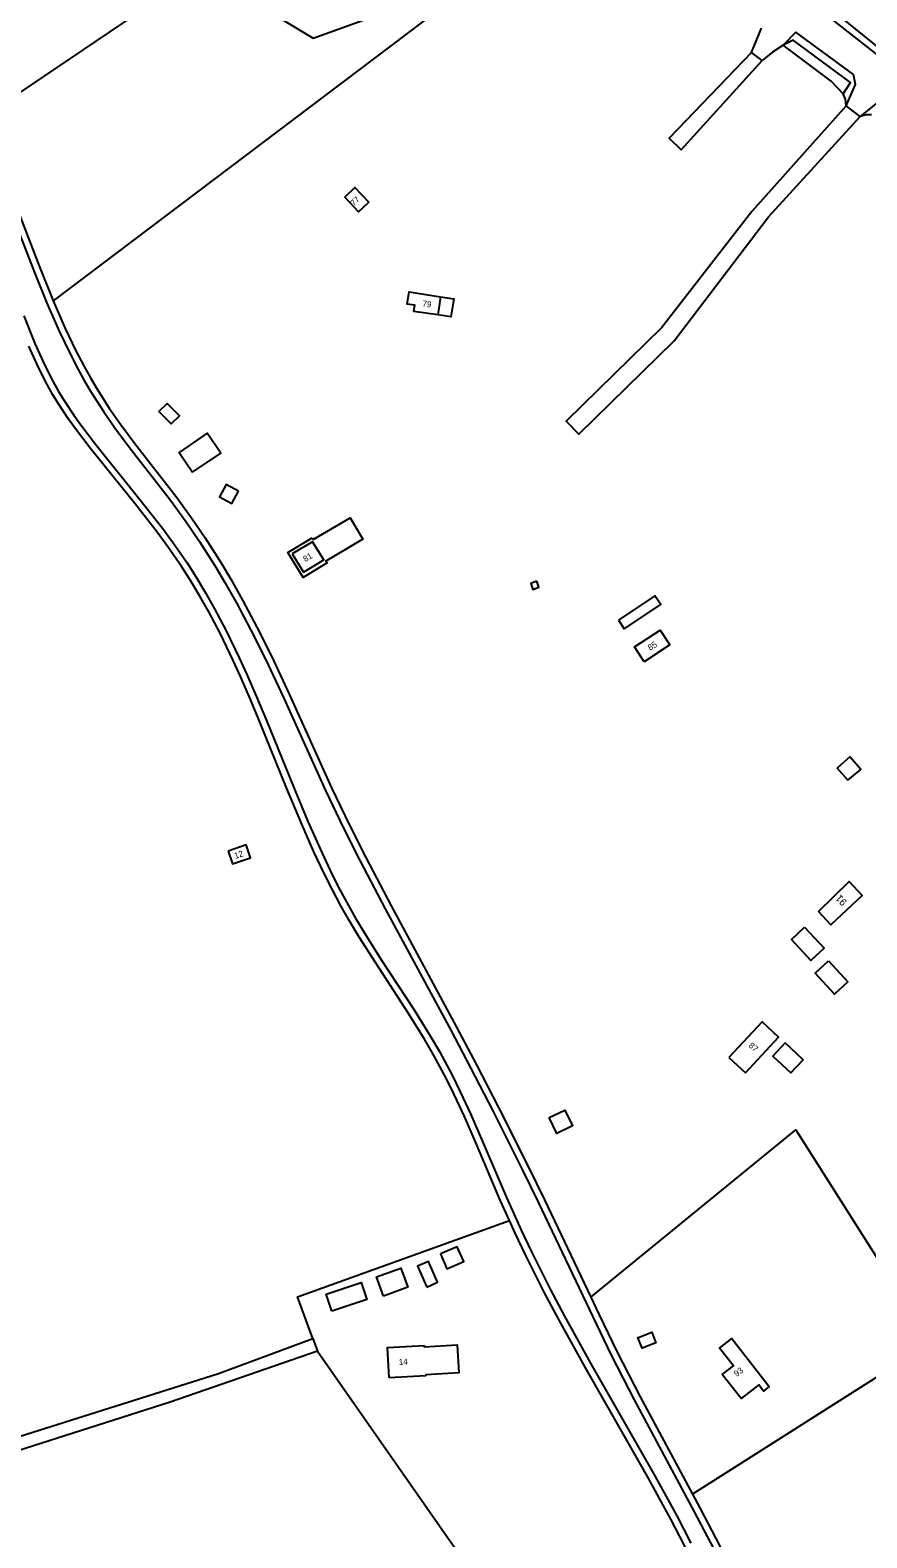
# Model space of a CAD drawing. Extents: x 124000 to 129000, y 395500 to 397503.
# Drawn here: x 128628.5 to 128766.7, y 395626.1 to 395875.2 of the extents above; entities that cross this region are included whole.
import ezdxf

# ---------------------------------------------------------------- set-up
doc = ezdxf.new("R2010")
doc.units = 0
for name, color, linetype in [('gg-afsc-draadraster', 7, 'Continuous'), ('gg-afsc-hekwerk', 7, 'Continuous'), ('gg-anno-huisnummerreeks BGT', 7, 'Continuous'), ('gg-bbg-bijgebouw', 7, 'Continuous'), ('gg-bbg-gedigitaliseerde bijgebouw', 7, 'Continuous'), ('gg-bbg-hoofdgebouw', 7, 'Continuous'), ('gg-bbg-luifel en loopbrug', 7, 'Continuous'), ('gg-bbg-overig bouwwerk', 7, 'Continuous'), ('gg-knt-onverhard', 7, 'Continuous'), ('gg-knt-verharding', 7, 'Continuous'), ('gg-kntw-bovenkant insteek waterloop', 7, 'Continuous'), ('gg-kntw-greppel-droge sloot', 7, 'Continuous'), ('gg-kntw-waterlijn', 7, 'Continuous'), ('gt-anno-plantopografie huisnummer', 7, 'Continuous'), ('gt-bbg-plantopografie pand', 7, 'Continuous'), ('gt-grn-vlakafsluiter', 7, 'Continuous')]:
    doc.layers.add(name, color=color, linetype=linetype)

msp = doc.modelspace()

# ---------------------------------------------------------------- linework, layer by layer
at = {"layer": 'gg-afsc-draadraster'}
msp.add_line((128747.71, 395871.46), (128749.35, 395875.49), dxfattribs=at)
for points in [[(128752.89, 395872.68), (128751.13, 395871.49), (128749.42, 395870.15)], [(128762.84, 395864.66), (128760.83, 395866.7), (128752.89, 395872.68)], [(128763.35, 395862.64), (128763.19, 395863.76), (128762.84, 395864.66)], [(128767.49, 395861.14), (128766.66, 395861.18), (128765.66, 395860.9)]]:
    msp.add_lwpolyline(points, dxfattribs=at)
at = {"layer": 'gg-afsc-hekwerk'}
for p, q in [((128749.42, 395870.15), (128747.71, 395871.46)), ((128765.66, 395860.9), (128763.35, 395862.64))]:
    msp.add_line(p, q, dxfattribs=at)
at = {"layer": 'gg-bbg-bijgebouw'}
for points in [[(128649.79, 395812.16), (128651.14, 395813.49), (128653.17, 395811.41), (128651.82, 395810.09), (128649.79, 395812.16)], [(128763.59, 395751.23), (128765.74, 395753.01), (128763.92, 395755.09), (128761.82, 395753.24), (128763.59, 395751.23)], [(128714.25, 395695.49), (128716.83, 395696.7), (128718.09, 395694.13), (128715.53, 395692.87), (128714.25, 395695.49)], [(128729.1, 395659.22), (128731.19, 395660.03), (128731.87, 395658.27), (128729.6, 395657.39), (128728.91, 395659.15), (128729.1, 395659.22)]]:
    msp.add_lwpolyline(points, dxfattribs=at)
at = {"layer": 'gg-bbg-gedigitaliseerde bijgebouw'}
for points in [[(128753.26, 395707.85), (128751.22, 395705.67), (128754.16, 395702.89), (128756.21, 395705.06), (128753.26, 395707.85)], [(128696.3, 395672.97), (128697.34, 395670.54), (128700.13, 395671.74), (128699.08, 395674.17), (128696.3, 395672.97)]]:
    msp.add_lwpolyline(points, dxfattribs=at)
at = {"layer": 'gg-bbg-hoofdgebouw'}
for p, q in [((128696.31, 395831.11), (128695.85, 395828.1)), ((128693.88, 395652.83), (128687.82, 395652.5))]:
    msp.add_line(p, q, dxfattribs=at)
for points in [[(128682.16, 395849.15), (128680.47, 395847.55), (128682.75, 395845.15), (128684.44, 395846.75), (128682.16, 395849.15)], [(128695.85, 395828.1), (128691.9, 395828.7), (128692.05, 395829.7), (128690.82, 395829.88), (128691.13, 395831.9), (128696.31, 395831.11)], [(128671.79, 395788.63), (128673.66, 395785.6), (128677, 395787.65), (128675.17, 395790.62), (128671.79, 395788.63)], [(128729.97, 395770.81), (128728.37, 395773.25), (128732.62, 395776.03), (128734.21, 395773.59), (128729.97, 395770.81)], [(128661.21, 395739.54), (128661.93, 395737.41), (128664.9, 395738.42), (128664.18, 395740.55), (128661.21, 395739.54)], [(128743.96, 395705.45), (128746.67, 395702.92), (128752.12, 395708.78), (128749.43, 395711.3), (128743.96, 395705.45)], [(128742.86, 395653.06), (128744.7, 395654.48), (128742.41, 395657.43), (128744.44, 395659.01), (128750.62, 395651.05), (128749.69, 395650.32), (128748.89, 395651.35), (128745.96, 395649.07), (128742.86, 395653.06)], [(128687.82, 395652.5), (128687.55, 395657.51), (128693.61, 395657.84)], [(128693.61, 395657.84), (128693.62, 395657.65), (128699.06, 395657.94), (128699.31, 395653.31), (128693.87, 395653.02), (128693.88, 395652.83)]]:
    msp.add_lwpolyline(points, dxfattribs=at)
at = {"layer": 'gg-bbg-luifel en loopbrug'}
for points in [[(128696.31, 395831.11), (128698.48, 395830.79), (128698.03, 395827.77), (128695.85, 395828.1)], [(128655.35, 395802.13), (128659.99, 395805.28), (128657.76, 395808.55), (128653.13, 395805.4), (128655.35, 395802.13)], [(128675.08, 395791.3), (128675.28, 395790.98), (128681.37, 395794.61), (128683.46, 395791.08), (128677.38, 395787.45), (128677.57, 395787.14), (128673.61, 395784.71), (128671.07, 395788.84), (128675.08, 395791.3)], [(128725.71, 395777.68), (128726.66, 395776.26), (128732.68, 395780.29), (128731.74, 395781.71), (128725.71, 395777.68)], [(128694.04, 395667.5), (128695.82, 395668.33), (128694.32, 395671.75), (128692.52, 395670.97), (128694.04, 395667.5)], [(128686.89, 395665.99), (128685.72, 395669.17), (128689.72, 395670.65), (128690.9, 395667.47), (128686.89, 395665.99)], [(128678.34, 395663.53), (128677.42, 395666.34), (128683.21, 395668.25), (128684.13, 395665.43), (128678.34, 395663.53)]]:
    msp.add_lwpolyline(points, dxfattribs=at)
at = {"layer": 'gg-bbg-overig bouwwerk'}
for points in [[(128662.94, 395798.97), (128660.89, 395800.08), (128659.77, 395798.08), (128661.8, 395796.94), (128662.94, 395798.97)], [(128712.2, 395784.11), (128711.21, 395783.74), (128711.58, 395782.75), (128712.57, 395783.12), (128712.2, 395784.11)]]:
    msp.add_lwpolyline(points, dxfattribs=at)
at = {"layer": 'gg-knt-onverhard'}
msp.add_line((128675.19, 395658.99), (128675.97, 395656.9), dxfattribs=at)
for points in [[(128954.35, 395760.78), (128948.98, 395764.44), (128925.7, 395777.97), (128910.15, 395787.23), (128877.36, 395803.24), (128864.3, 395808.96), (128847.57, 395816.53), (128832.35, 395823.92), (128813.92, 395836.35), (128802.82, 395844.06), (128782.88, 395859.45), (128770.3, 395869.66), (128754.99, 395881.7), (128739.9, 395893.06), (128722.48, 395906.81), (128714.46, 395913.11), (128696.72, 395926.81), (128676.46, 395942.51), (128659.09, 395956.88), (128648.97, 395968.49), (128642.86, 395979.71), (128637.73, 395993.56)], [(128747.71, 395871.46), (128734.08, 395857.29), (128736.07, 395855.38), (128749.42, 395870.15)], [(128763.35, 395862.64), (128747.74, 395845.17), (128732.85, 395826.03), (128717.04, 395810.57), (128719.14, 395808.42), (128734.91, 395823.84), (128750.48, 395844.29), (128765.66, 395860.9)], [(128589.5, 395630.4), (128623.51, 395641.83), (128659.63, 395653.21), (128675.19, 395658.99)], [(128675.97, 395656.9), (128651.65, 395648.5), (128619.67, 395638.29), (128591.07, 395627.09)]]:
    msp.add_lwpolyline(points, dxfattribs=at)
at = {"layer": 'gg-knt-verharding'}
for points in [[(128763.35, 395862.64), (128764.85, 395866.19), (128764.54, 395867.82), (128755, 395874.81), (128752.89, 395872.68)], [(128769.73, 395863.44), (128768.57, 395863.28), (128765.66, 395860.9)]]:
    msp.add_lwpolyline(points, dxfattribs=at)
at = {"layer": 'gg-kntw-bovenkant insteek waterloop'}
for points in [[(128620.02, 395860.3), (128621.73, 395856.69), (128622.95, 395853.95), (128624.5, 395850.26), (128626.35, 395845.61), (128630.05, 395836.04), (128632.29, 395830.46)], [(128632.29, 395830.46), (128634.3, 395825.87), (128636.02, 395822.27), (128637.4, 395819.61), (128638.41, 395817.81), (128639.43, 395816.09), (128641.58, 395812.71), (128643.42, 395810.08), (128645.81, 395806.87), (128652.56, 395798.18), (128655.18, 395794.57), (128657.43, 395791.26), (128660.1, 395787.03), (128661.64, 395784.45), (128663.61, 395780.96), (128665.97, 395776.54), (128668.38, 395771.71), (128671.34, 395765.37), (128677.51, 395751.69), (128678.29, 395750), (128681.26, 395743.82), (128683.96, 395738.46), (128688.15, 395730.5), (128698.97, 395710.44), (128702.23, 395704.24), (128705.9, 395697.14), (128710.84, 395687.31), (128713.47, 395681.91), (128721.12, 395665.82)], [(128707.69, 395678.52), (128706.18, 395681.88), (128702.25, 395691.1), (128700.24, 395695.68), (128698.56, 395699.31), (128697.23, 395701.99), (128695.15, 395705.87), (128693.65, 395708.46), (128691.01, 395712.7), (128685.54, 395721.1), (128682.86, 395725.32), (128681.32, 395727.89), (128679.84, 395730.51), (128678.44, 395733.15), (128677.1, 395735.82), (128675.4, 395739.43), (128673.37, 395744), (128670.86, 395750), (128666.51, 395760.7), (128664.89, 395764.57), (128663.29, 395768.26), (128662.04, 395771), (128659.87, 395775.51), (128658.01, 395779.05), (128656.54, 395781.66), (128655, 395784.22), (128653.52, 395786.52), (128651.25, 395789.8), (128649.48, 395792.21), (128645.79, 395796.96), (128638.42, 395806.09), (128635.99, 395809.28), (128634.83, 395810.91), (128633.18, 395813.4), (128632.26, 395814.9), (128631.29, 395816.64), (128629.93, 395819.29), (128628.29, 395822.92)], [(128764.86, 395575.56), (128763.59, 395577.11), (128761.1, 395580.24), (128757.15, 395585.42), (128754.81, 395588.68), (128752.57, 395592), (128751.51, 395593.69), (128750.09, 395596.07), (128748.2, 395599.59), (128746.87, 395602.27), (128744.78, 395606.81), (128740.77, 395615.99), (128738.42, 395621.13), (128736.65, 395624.72), (128734.36, 395629.16), (128730.52, 395636.18), (128720.19, 395654.27), (128715.83, 395662.15), (128713.49, 395666.56), (128710.34, 395672.81), (128708.62, 395676.43), (128707.69, 395678.52)], [(128721.12, 395665.82), (128722.44, 395663.05), (128725.51, 395656.76), (128729.28, 395649.37), (128737.91, 395633.31)], [(128737.91, 395633.31), (128739.2, 395630.9), (128742.44, 395624.68), (128744.22, 395621.09), (128746.37, 395616.56), (128750.67, 395606.93), (128752.37, 395603.3), (128753.72, 395600.63), (128755.16, 395598.02), (128756.26, 395596.2), (128757.91, 395593.73), (128759.67, 395591.34), (128762.18, 395588.26), (128764.16, 395586.01), (128765.21, 395584.88)]]:
    msp.add_lwpolyline(points, dxfattribs=at)
at = {"layer": 'gg-kntw-greppel-droge sloot'}
for points in [[(128770.35, 395870.89), (128755.7, 395882.78), (128740.64, 395894.3), (128722.62, 395908.52), (128695.05, 395930.42), (128676.59, 395944.87), (128666.59, 395952.95), (128658.64, 395958.92)], [(128762.84, 395864.66), (128764.04, 395866.5), (128754.57, 395873.52), (128752.89, 395872.68)]]:
    msp.add_lwpolyline(points, dxfattribs=at)
at = {"layer": 'gg-kntw-waterlijn'}
for points in [[(128625.33, 395845.2), (128629.02, 395835.64), (128631.28, 395830.04), (128633.29, 395825.42), (128635.04, 395821.78), (128636.43, 395819.09), (128637.45, 395817.26), (128638.49, 395815.51), (128640.67, 395812.1), (128642.52, 395809.43), (128644.93, 395806.2), (128651.68, 395797.52), (128654.28, 395793.94), (128656.51, 395790.66), (128659.16, 395786.46), (128660.69, 395783.9), (128662.65, 395780.43), (128664.99, 395776.04), (128667.38, 395771.23), (128670.34, 395764.91), (128676.51, 395751.24), (128677.3, 395749.53), (128680.27, 395743.33), (128682.98, 395737.96), (128687.18, 395729.98), (128698, 395709.92), (128701.26, 395703.74), (128704.92, 395696.64), (128709.85, 395686.82), (128712.48, 395681.43), (128721.45, 395662.58), (128724.52, 395656.27), (128728.3, 395648.86), (128738.23, 395630.38), (128741.46, 395624.18)], [(128627.44, 395827.97), (128629.3, 395823.36), (128630.93, 395819.77), (128632.26, 395817.16), (128633.21, 395815.46), (128634.11, 395813.99), (128635.74, 395811.53), (128636.88, 395809.93), (128639.28, 395806.77), (128646.65, 395797.64), (128650.36, 395792.88), (128652.15, 395790.44), (128654.44, 395787.13), (128655.93, 395784.8), (128657.49, 395782.21), (128658.98, 395779.57), (128660.85, 395776), (128663.04, 395771.47), (128664.29, 395768.7), (128665.9, 395765), (128667.53, 395761.12), (128671.88, 395750.42), (128674.38, 395744.43), (128676.4, 395739.89), (128678.09, 395736.3), (128679.42, 395733.65), (128680.81, 395731.04), (128682.27, 395728.44), (128683.8, 395725.9), (128686.46, 395721.69), (128691.93, 395713.3), (128694.59, 395709.02), (128696.11, 395706.41), (128698.21, 395702.49), (128699.55, 395699.78), (128701.25, 395696.13), (128703.26, 395691.54), (128707.19, 395682.32), (128709.62, 395676.89), (128711.33, 395673.3), (128714.47, 395667.07), (128716.8, 395662.67), (128721.15, 395654.8), (128731.48, 395636.72), (128735.33, 395629.68), (128737.64, 395625.21)]]:
    msp.add_lwpolyline(points, dxfattribs=at)
at = {"layer": 'gt-bbg-plantopografie pand'}
for points in [[(128758.74, 395729.55), (128763.82, 395734.53), (128765.99, 395732.18), (128760.77, 395727.35), (128758.74, 395729.55)], [(128756.46, 395726.94), (128759.67, 395723.48), (128757.48, 395721.45), (128754.27, 395724.91), (128756.46, 395726.94)], [(128760.39, 395721.38), (128763.6, 395717.93), (128761.41, 395715.9), (128758.2, 395719.35), (128760.39, 395721.38)]]:
    msp.add_lwpolyline(points, dxfattribs=at)
at = {"layer": 'gt-grn-vlakafsluiter'}
msp.add_line((128698.68, 395880.59), (128632.29, 395830.46), dxfattribs=at)
for points in [[(128620.02, 395860.3), (128656.73, 395885.09), (128675.29, 395873.84), (128692.56, 395880.03), (128696.65, 395882.87)], [(128721.12, 395665.82), (128755.01, 395693.49), (128777.32, 395658.28), (128737.91, 395633.31)], [(128675.19, 395658.99), (128672.7, 395665.91), (128707.69, 395678.52)], [(128675.97, 395656.9), (128716.66, 395598.64), (128728.27, 395601.96), (128739.81, 395580.32), (128700.36, 395553.94), (128707.47, 395539.83)]]:
    msp.add_lwpolyline(points, dxfattribs=at)

# ---------------------------------------------------------------- texts
at = {"layer": 'gg-anno-huisnummerreeks BGT'}
for s, rotation, p in [('77', 43.5, (128681.99, 395846.02)), ('79', 351.4, (128693.26, 395829.53)), ('81', 31.6, (128673.98, 395787.25)), ('85', 33.2, (128730.95, 395772.59)), ('12', 18.7, (128662.41, 395738.23)), ('87', 316.9, (128747.13, 395707.28)), ('14', 3.1, (128689.43, 395654.6)), ('93', 37.8, (128745.25, 395652.63))]:
    msp.add_text(s, height=1, rotation=rotation, dxfattribs=at).set_placement(p)
at = {"layer": 'gt-anno-plantopografie huisnummer'}
msp.add_text('91', height=1.2, rotation=132.7454, dxfattribs=at).set_placement((128763.54, 395731.14))

doc.saveas('drawing.dxf')
